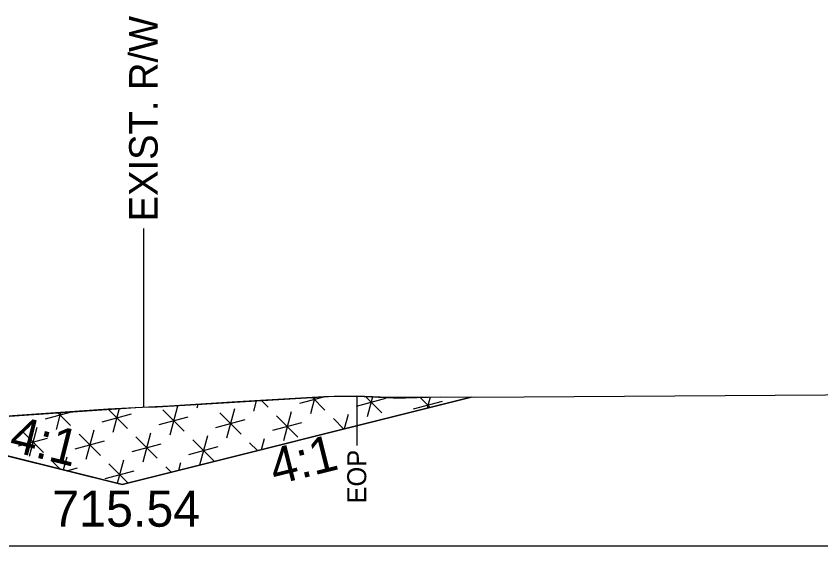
# Model space of a CAD drawing. Extents: x -26 to 4303, y -10 to 9577.
# Drawn here: x 4174.61 to 4207.98, y 5000 to 5021.96 of the extents above; entities that cross this region are included whole.
import ezdxf

# ---------------------------------------------------------------- set-up
doc = ezdxf.new("R2010")
doc.units = 0
for name, color, linetype in [('Old_Level_2', 7, 'Continuous'), ('Pattern 3', 7, 'Continuous'), ('Prop CMT Pvmt Course 2 Wedge', 7, 'Continuous'), ('Prop CMT Slope Grass', 7, 'Continuous'), ('Prop XS DDE Elevations', 7, 'Continuous'), ('Prop XS Ditch Standard Text', 7, 'Continuous'), ('Prop XS Hydro Elevations', 7, 'Continuous'), ('Prop XS Side Slope Text', 7, 'Continuous')]:
    doc.layers.add(name, color=color, linetype=linetype)

msp = doc.modelspace()

# ---------------------------------------------------------------- linework, layer by layer
at = {"layer": 'Old_Level_2'}
msp.add_line((4150, 5000), (4300, 5000), dxfattribs=at)
msp.add_line((4150, 5000), (4300, 5000), dxfattribs=at)
at = {"layer": 'Pattern 3'}
for p, q in [((4184.78, 5006.027), (4185.056, 5005.751)), ((4186.366, 5005.913), (4187.371, 5006.182)), ((4186.993, 5006.159), (4186.808, 5005.471)), ((4186.891, 5006.153), (4187.412, 5005.632)), ((4188.723, 5005.794), (4189.93, 5006.118)), ((4189.092, 5006.19), (4189.769, 5005.514)), ((4189.386, 5006.176), (4189.165, 5005.352)), ((4191.364, 5006.157), (4191.781, 5005.739)), ((4191.772, 5006.168), (4191.648, 5005.706)), ((4178.884, 5005.694), (4178.62, 5004.707)), ((4181.3, 5005.796), (4180.976, 5004.588)), ((4182.139, 5005.868), (4182.095, 5005.707)), ((4182.668, 5005.9), (4182.699, 5005.869)), ((4184.566, 5006.014), (4184.452, 5005.589)), ((4191.079, 5005.676), (4192.287, 5005.999)), ((4175.822, 5005.267), (4176.909, 5005.558)), ((4176.452, 5005.527), (4176.264, 5004.825)), ((4176.335, 5005.519), (4176.867, 5004.987)), ((4178.178, 5005.149), (4179.385, 5005.472)), ((4178.43, 5005.663), (4179.224, 5004.869)), ((4180.534, 5005.03), (4181.742, 5005.354)), ((4180.696, 5005.634), (4181.58, 5004.75)), ((4183.053, 5005.516), (4183.937, 5004.632)), ((4183.656, 5005.677), (4183.333, 5004.47)), ((4185.409, 5005.397), (4186.293, 5004.513)), ((4186.013, 5005.559), (4185.689, 5004.352)), ((4188.369, 5005.441), (4188.21, 5004.846)), ((4182.891, 5004.912), (4184.098, 5005.235)), ((4185.247, 5004.794), (4186.455, 5005.117)), ((4187.766, 5005.279), (4188.201, 5004.844)), ((4174.864, 5004.752), (4175.748, 5003.868)), ((4175.468, 5004.914), (4175.144, 5003.706)), ((4177.824, 5004.795), (4177.501, 5003.588)), ((4188.69, 5004.966), (4188.811, 5004.999)), ((4174.703, 5004.148), (4175.91, 5004.472)), ((4177.059, 5004.03), (4178.266, 5004.353)), ((4177.221, 5004.633), (4178.105, 5003.75)), ((4179.577, 5004.515), (4180.461, 5003.631)), ((4180.181, 5004.677), (4179.857, 5003.469)), ((4181.934, 5004.397), (4182.818, 5003.513)), ((4182.537, 5004.558), (4182.214, 5003.351)), ((4184.894, 5004.44), (4184.772, 5003.987)), ((4179.415, 5003.911), (4180.623, 5004.235)), ((4181.772, 5003.793), (4182.979, 5004.116)), ((4184.29, 5004.278), (4184.62, 5003.949)), ((4176.102, 5003.514), (4176.43, 5003.186)), ((4176.705, 5003.676), (4176.565, 5003.152)), ((4178.458, 5003.396), (4179.248, 5002.606)), ((4179.062, 5003.558), (4178.803, 5002.593)), ((4181.418, 5003.439), (4181.335, 5003.127)), ((4176.708, 5003.117), (4177.147, 5003.234)), ((4178.296, 5002.792), (4179.504, 5003.116)), ((4180.815, 5003.278), (4181.039, 5003.053))]:
    msp.add_line(p, q, dxfattribs=at)
msp.add_lwpolyline([(4171.308, 5003.783), (4174.283, 5003.723), (4179, 5002.544), (4193.479, 5006.163), (4190.033, 5006.145), (4188.732, 5006.208), (4187.371, 5006.182), (4183.784, 5005.967), (4180.952, 5005.797), (4178.43, 5005.663), (4174.454, 5005.39), (4169.991, 5005.085), (4165.462, 5004.774), (4164.383, 5004.701), (4163.016, 5004.608), (4163.016, 5003.948)], close=True, dxfattribs=at)
at = {"layer": 'Prop CMT Pvmt Course 2 Wedge'}
msp.add_lwpolyline([(4169, 5004.704), (4171, 5004.544), (4179, 5002.544), (4193.479, 5006.163)], dxfattribs=at)
at = {"layer": 'Prop CMT Slope Grass'}
msp.add_lwpolyline([(4163.026, 5004.608), (4179.578, 5005.741), (4180.123, 5005.76), (4180.454, 5005.767), (4187.795, 5006.207), (4188.732, 5006.208), (4190.24, 5006.135), (4190.757, 5006.14), (4192.19, 5006.18), (4193.585, 5006.162), (4222.742, 5006.36)], dxfattribs=at)
at = {"layer": 'Prop XS DDE Elevations'}
msp.add_lwpolyline([(4192.19, 5006.18), (4193.479, 5006.163), (4179, 5002.544), (4174.465, 5003.677), (4171, 5004.544), (4169, 5004.704), (4167, 5004.744), (4165.462, 5004.774), (4179.578, 5005.741), (4180.123, 5005.76), (4180.454, 5005.767), (4187.795, 5006.207), (4188.732, 5006.208), (4190.24, 5006.135), (4190.757, 5006.14)], close=True, dxfattribs=at)
at = {"layer": 'Prop XS Ditch Standard Text'}
for p, q in [((4179.884, 5013.153), (4179.884, 5005.752)), ((4188.732, 5006.208), (4188.732, 5004.157))]:
    msp.add_line(p, q, dxfattribs=at)

# ---------------------------------------------------------------- texts
for s, height, p in [('EXIST. R/W', 1.1811, (4180.475, 5013.455)), ('EOP', 0.7874, (4189.125, 5001.759))]:
    msp.add_text(s, height=height, rotation=90, dxfattribs=at).set_placement(p)
at = {"layer": 'Prop XS Hydro Elevations'}
msp.add_text('715.54', height=1.5, dxfattribs=at).set_placement((4176.105, 5000.796))
at = {"layer": 'Prop XS Side Slope Text'}
for rotation, p in [(345.9638, (4174.263, 5003.957)), (14.0362, (4185.339, 5002.516))]:
    msp.add_text('4:1', height=1.5, rotation=rotation, dxfattribs=at).set_placement(p)

doc.saveas('drawing.dxf')
